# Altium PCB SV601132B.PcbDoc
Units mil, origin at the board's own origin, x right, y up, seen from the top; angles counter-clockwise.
Board outline 2180 x 2750 mil, 2 copper layers (Top Layer, Bottom Layer), stack 61.4 mil thick; 47 components, 16 nets, 82 pads, 27 vias.
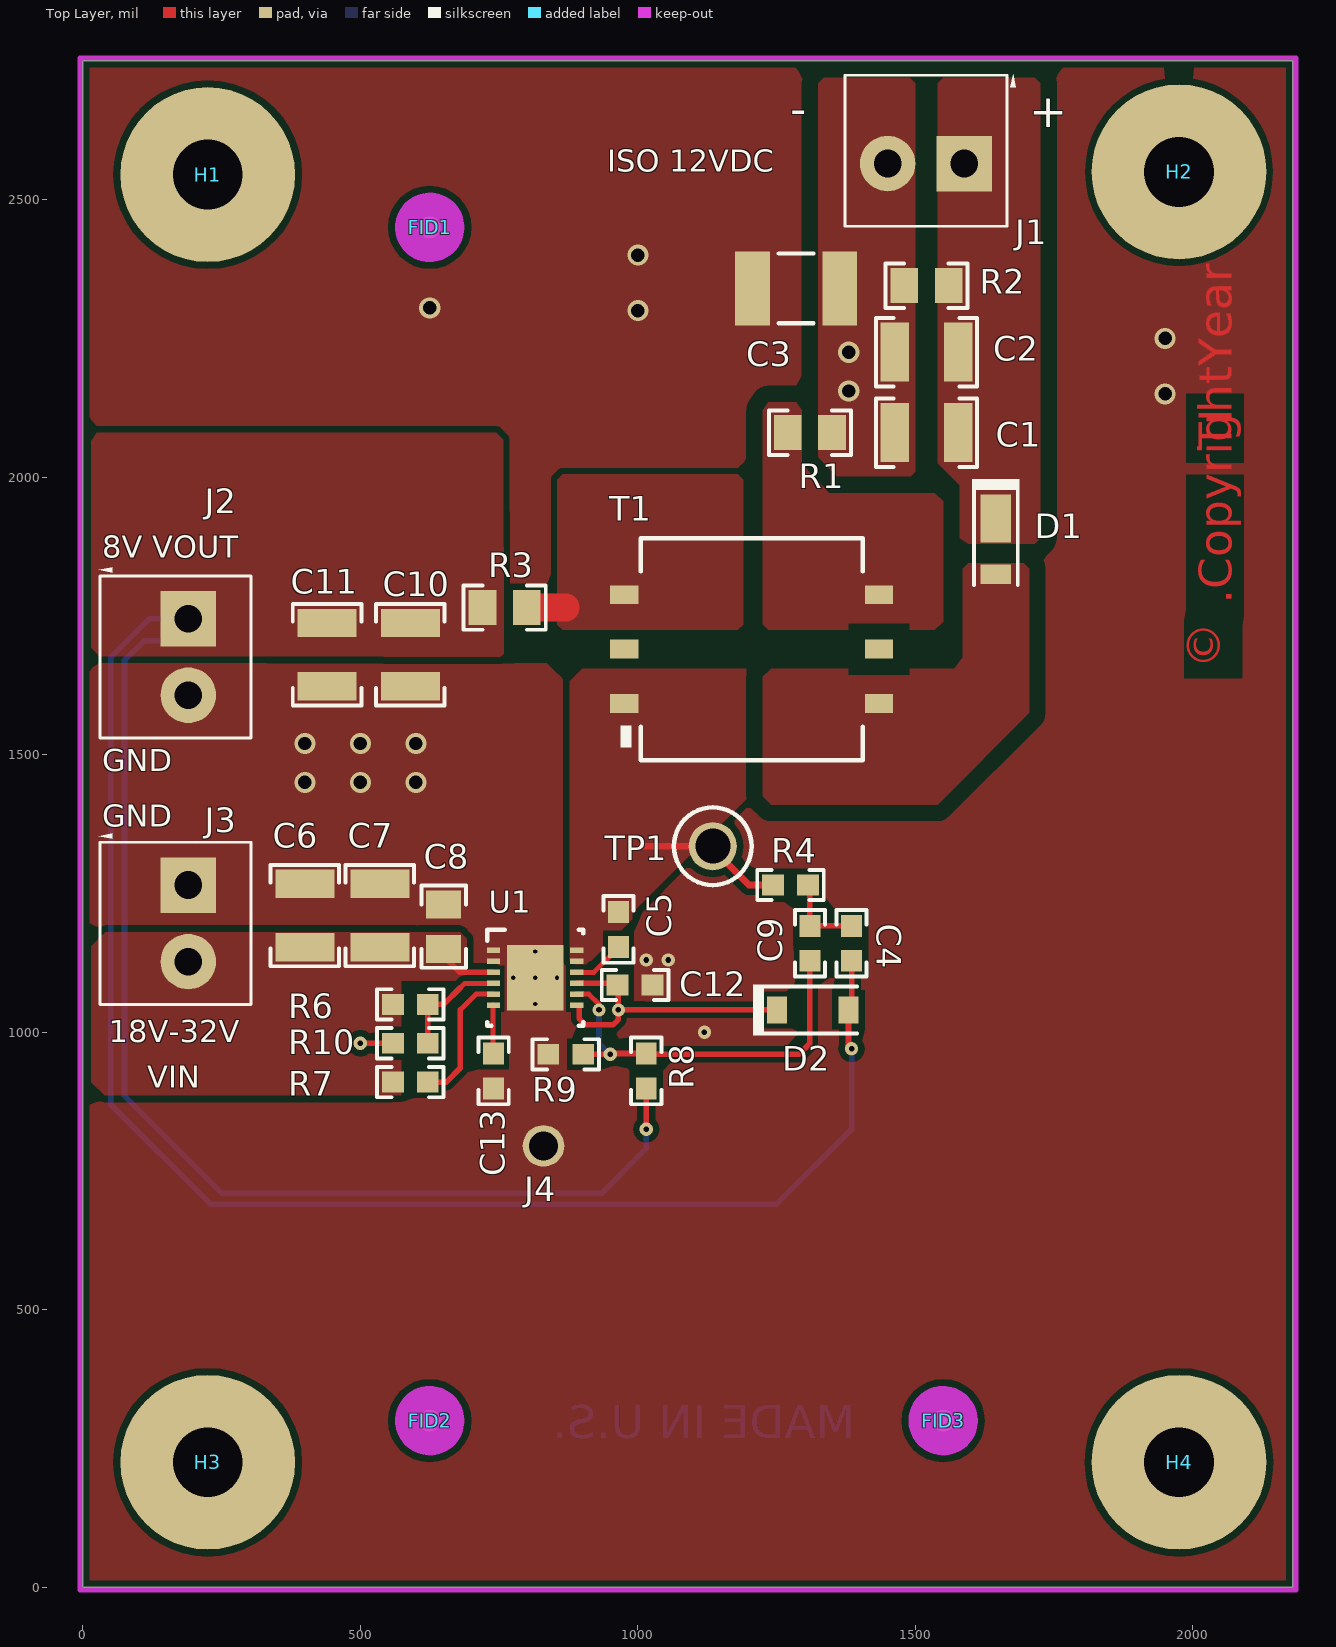
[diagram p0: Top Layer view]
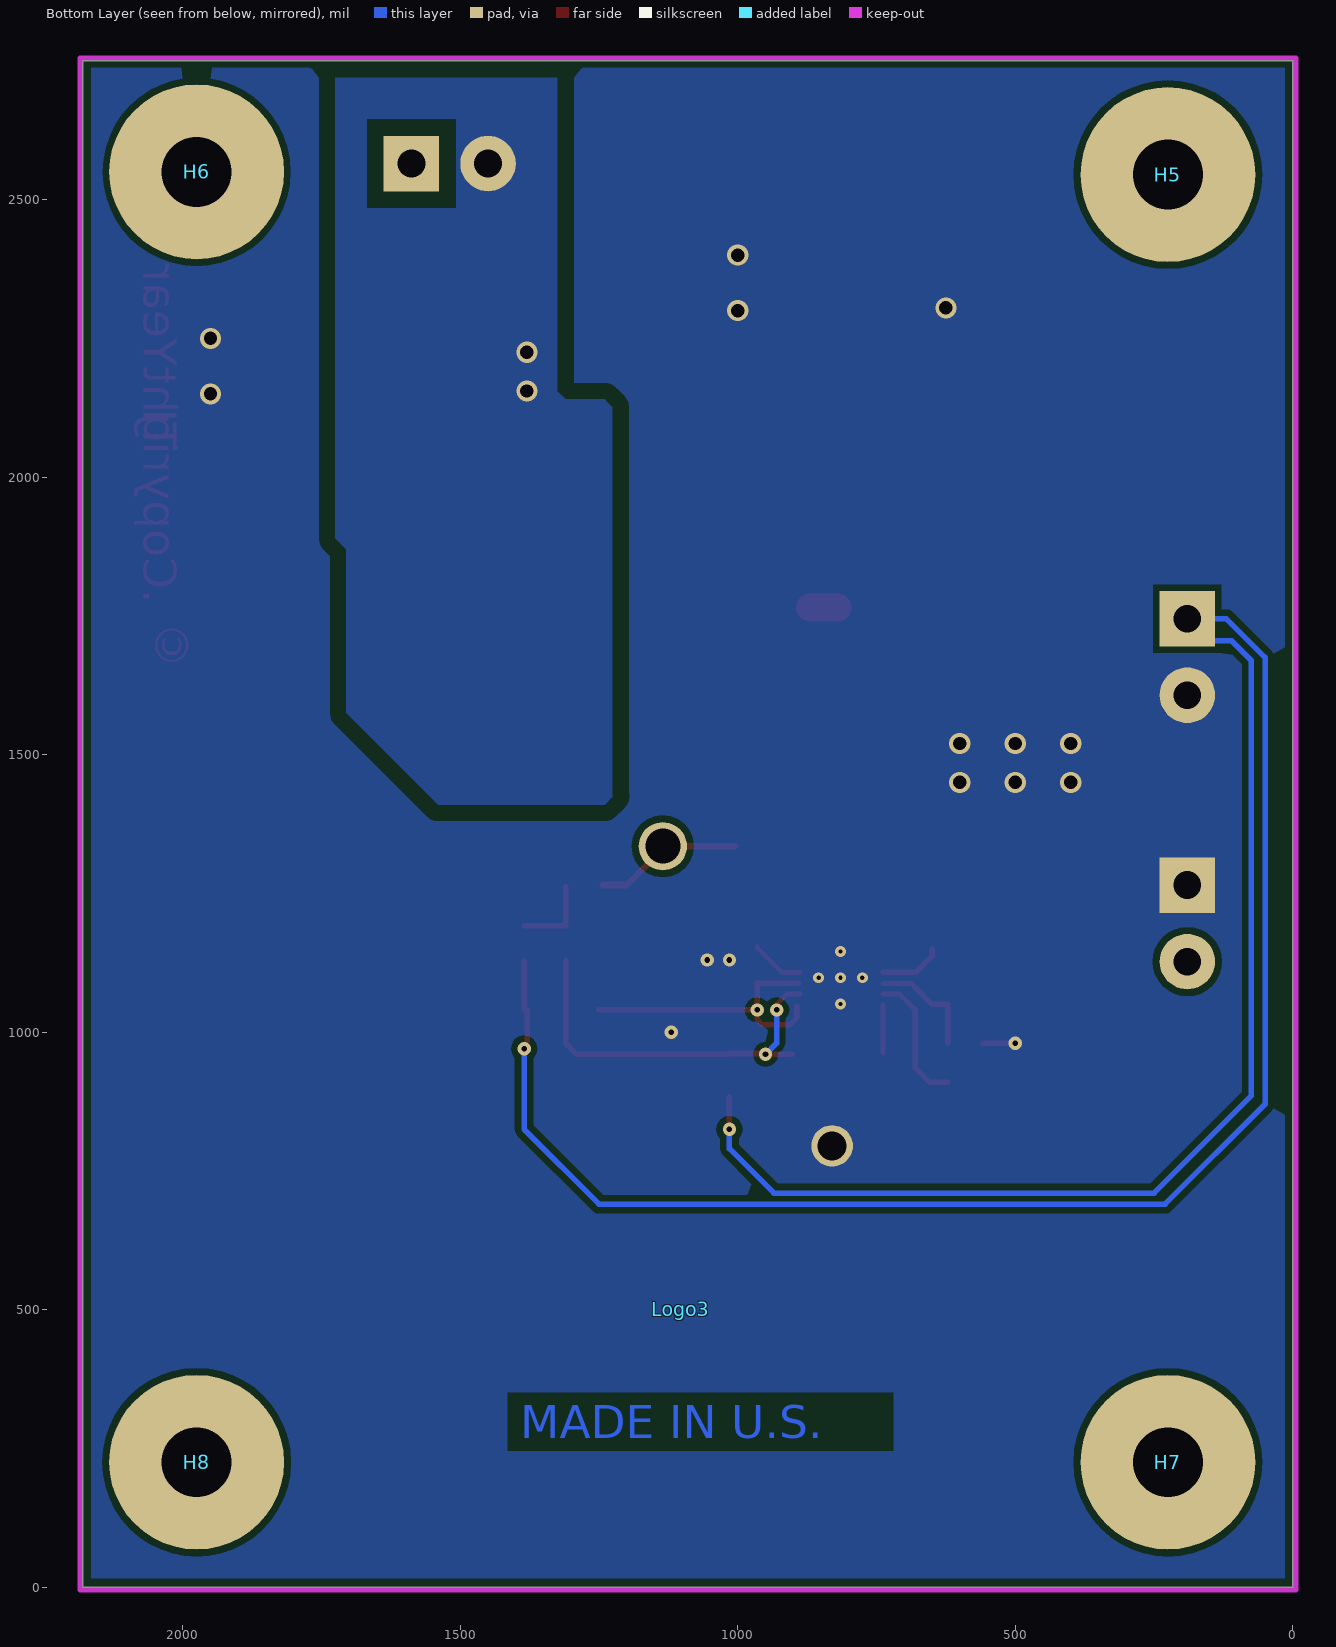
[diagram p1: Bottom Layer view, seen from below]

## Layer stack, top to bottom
Top Solder: solder mask 0.4, Solder Resist, Dk 3.5
Top Layer: signal copper 2.8
Dielectric1: core 55.8, FR-4, Dk 4.8
Bottom Layer: signal copper 2.8
Bottom Solder: solder mask 0.4, Solder Resist, Dk 3.5

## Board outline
0,0 0,2750 2180,2750 2180,0

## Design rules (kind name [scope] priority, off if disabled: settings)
AcuteAngle [All] p1: minimum=4.50000000000000E+0001 checktracksonly=FALSE
AssemblyTestPointUsage [All] p1: valid=2
Clearance "clearance U1" [HasFootprint('DNT0012B')] p1: gap=8 ignorepadtopadclearanceinfootprint=FALSE
Clearance [InNet('ISOGND')   or InNet('NetD1_2')    or   InNet('NetR1_1')      or InNet ('VOUTISO')] p2: gap=30 ignorepadtopadclearanceinfootprint=FALSE
Clearance Clearance_2 [InNet('NetR6_1')  or InNet('NetR7_1') or InNet('NetC6_1')    or   InNet('NetC13_1')     or InNet('NetC9_2')  or InNet('NetC12_1')       or InNet('NetC5_2')] p3: gap=10 ignorepadtopadclearanceinfootprint=FALSE
Clearance Clearance_1 [All] p4: gap=12 ignorepadtopadclearanceinfootprint=FALSE
Clearance Clearance_BoardEdge_MountingHoles [OnCopper and InComponentClass('Mounting Holes') vs IsKeepOut] p5: gap=30 ignorepadtopadclearanceinfootprint=FALSE
Clearance Clearance_BoardEdge_Poly [OnCopper and InPoly vs IsKeepOut] p6: gap=25 ignorepadtopadclearanceinfootprint=FALSE
Clearance Clearance_BoardEdge [OnCopper and Not InComponentClass('Logo') and not InComponentClass('FiducialMark') and not InRegion(100,500,4000,8000) and Not IsKeepOut vs IsKeepOut] p7: gap=40 ignorepadtopadclearanceinfootprint=FALSE
Clearance Clearance_Poly [InPolygon] p8: gap=12 ignorepadtopadclearanceinfootprint=FALSE
ComponentClearance ComponentClearance_Logo [InComponentClass('Logo')] p1: gap=50 collisioncheckmode=3 verticalgap=10 showdistances=FALSE
ComponentClearance ComponentClearance_ScrewToNut [(HasFootprint('NY PMS 440 0025 PH')) vs (HasFootprint('Keystone_1902C'))] p2: gap=5 collisioncheckmode=3 verticalgap=10 showdistances=FALSE
ComponentClearance ComponentClearance_MountingHoles [InComponentClass('Mounting Holes')] p3: gap=130 collisioncheckmode=3 verticalgap=100000 showdistances=FALSE
ComponentClearance ComponentClearance_SmallPassives [HasFootprint('0201*') or HasFootprint('0402*') or HasFootprint('0508') or HasFootprint('0603*') or HasFootprint('0612') or HasFootprint('0805*') or HasFootprint('0815*') or HasFootprint('0830*') or HasFootprint('1206*') or HasFootprint('1210*') or HasFootprint('1808*') or HasFootprint('1812*') or HasFootprint('1825*') or HasFootprint('2010*') or HasFootprint('2220*') or HasFootprint('2225*') or HasFootprint('2512*') or HasFootprint('2728*') or HasFootprint('3518*') vs HasFootprint('0201*') or HasFootprint('0402*') or HasFootprint('0508') or HasFootprint('0603*') or HasFootprint('0612') or HasFootprint('0805*') or HasFootprint('0815*') or HasFootprint('0830*') or HasFootprint('1206*') or HasFootprint('1210*') or HasFootprint('1808*') or HasFootprint('1812*') or HasFootprint('1825*') or HasFootprint('2010*') or HasFootprint('2220*') or HasFootprint('2225*') or HasFootprint('2512*') or HasFootprint('2728*') or HasFootprint('3518*')] p4: gap=20 collisioncheckmode=3 verticalgap=10 showdistances=FALSE
ComponentClearance ComponentClearance_THtoSMT [IsThruComponent vs IsSMTComponent] p5: gap=50 collisioncheckmode=3 verticalgap=30 showdistances=FALSE
ComponentClearance ComponentClearance_THtoTH [IsThruComponent vs IsThruComponent] p6: gap=118.11 collisioncheckmode=3 verticalgap=30 showdistances=FALSE
ComponentClearance [All] p7: gap=20 collisioncheckmode=3 verticalgap=10 showdistances=FALSE
ComponentOrientations [All] p1: allowedrotations=32
DiffPairsRouting [All] p1: maxlimit=100 minlimit=10 mostfreqgap=10 toplayer_minwidth=15 toplayer_maxwidth=15 toplayer_prefwidth=15 bottomlayer_minwidth=15 bottomlayer_maxwidth=15 bottomlayer_prefwidth=15 maxuncoupledlength=1000
FabricationTestPointUsage TestPointUsage [All] p1: valid=2 allowmultiple=FALSE
FabricationTestpoint Testpoint [All] p1: side=3 testpointundercomponent=TRUE minsize=40 maxsize=100 preferedsize=60 minholesize=0 maxholesize=40 preferedholesize=32 testpointgrid=1 allowsidetop=TRUE allowsidebottom=TRUE usegrid=TRUE gridtolerance=0.01
FanoutControl Fanout_LCC [IsLCC] p1: bgadir=Out bgaviamode=Centered fanoutstyle=Auto fanoutdirection=Alternating viagrid=1 // Fanout_LCC (Default Rule)
FanoutControl Fanout_BGA [IsBGA] p2: bgadir=Out bgaviamode=Centered fanoutstyle=Auto fanoutdirection=Alternating viagrid=1 // Fanout_BGA (Default Rule)
FanoutControl Fanout_Default [All] p4: bgadir=Out bgaviamode=Centered fanoutstyle=Auto fanoutdirection=Alternating viagrid=1 // Fanout_Default (Default Rule)
FanoutControl Fanout_Small [(CompPinCount < 5)] p5: bgadir=Out bgaviamode=Centered fanoutstyle=Auto fanoutdirection=OutThenIn viagrid=1 // Fanout_Small (Default Rule)
HoleSize [All] p1: absolutevalues=TRUE maxlimit=251 minlimit=7 maxpercent=80.000 minpercent=20.000
MinimumAnnularRing MinimumAnnularRing_ThermalPadVias [IsVia and InAnyComponent] p1: minimumring=5.91
MinimumAnnularRing [All] p2: minimumring=6
MinimumSolderMaskSliver MinimumSolderMaskSliver_Logo [InComponentClass('Logo') vs InComponentClass('Logo')] p1: minsoldermaskwidth=0.7
MinimumSolderMaskSliver [All] p2: minsoldermaskwidth=3.94
PlaneConnect [All] p1: planeconnectstyle=Direct reliefexpansion=10 reliefentries=4 reliefconductorwidth=10 reliefairgap=10
PolygonConnect PolygonConnect_2 [All vs IsNamedPolygon('Top Layer-No Net')] p1: connectstyle=Direct reliefconductorwidth=10 reliefentries=4 polygonreliefangle="90 Angle" airgapwidth=10
PolygonConnect PolygonConnect_1 [All vs IsNamedPolygon('Top Layer-No Net')] p2: connectstyle=Direct reliefconductorwidth=10 reliefentries=4 polygonreliefangle="90 Angle" airgapwidth=10
PolygonConnect [All] p3: connectstyle=Direct reliefconductorwidth=10 reliefentries=4 polygonreliefangle="90 Angle" airgapwidth=10
RoutingVias ThermalPadVias [IsVia and InAnyComponent] p1: holewidth=7.87 width=19.68 viastyle="Through Hole" minholewidth=7.87 minwidth=19.68 maxholewidth=12.99 maxwidth=23.62
RoutingVias [All] p2: holewidth=16 width=34 viastyle="Through Hole" minholewidth=7.87 minwidth=20 maxholewidth=40 maxwidth=65
SMDToCorner [All] p1: distance=30000
SilkToBoardRegionClearance [NOT ((IsComment OR IsDesignator) AND (Hide <> 'FAIL')) AND NOT InRegion (100,500,4000,8000)] p1:
SilkToSilkClearance [All] p1: silktosilkclearance=5
SilkToSolderMaskClearance SilkscreenOverComponentPads [IsPad] p1: minsilkscreentomaskgap=5 clearancetoexposedcopper=TRUE
SolderMaskExpansion [All] p1: expansion=1.97 istentingtop=FALSE
Width [All] p1: maxlimit=100 minlimit=6 preferedwidth=10 checkconnectedcopper=TRUE
15 further rules are at their usual default settings.

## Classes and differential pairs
component class AssemblyNote: ZZ1 ZZ2 ZZ3 ZZ4
component class FiducialMark: FID1 FID2 FID3
component class SV601132B_HW: FID1 FID2 FID3 H1 H2 H3 H4 H5 H6 H7 H8 Logo3 ZZ1 ZZ2 ZZ3 ZZ4
component class "Mounting Holes": H1 H2 H3 H4
component class SV601132B: C1 C2 C3 C4 C5 C6 C7 C8 C9 C10 C11 C12 C13 D1 D2 J1 J2 J3 J4 R1 R2 R3 R4 R6 R7 R8 R9 R10 T1 TP1 U1

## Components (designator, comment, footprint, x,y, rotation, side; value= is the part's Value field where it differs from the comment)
C1 "GRM32ER7YA106KA12L" 1210 1520,2080 r0 top
C2 "GRM32ER7YA106KA12L" 1210 1520,2225 r0 top
C3 "C4532X7R3D222K" 1812 1285,2340 r0 top
C4 "GRM188R71C102KA01D" 0603 1385,1160 r270 top
C5 "GRM188R71C103KA01D" 0603 965,1185 r270 top
C6 "GRM32ER72A225KA35K" 1210 400,1210 r90 top
C7 "GRM32ER72A225KA35K" 1210 535,1210 r90 top
C8 "GRM21BR72A474KA73L" 0805_HV 650,1190 r90 top
C9 "06033C104JAT2A" 0603 1310,1160 r270 top
C10 "GRM32ER7YA106KA12L" 1210 590,1680 r270 top
C11 "GRM32ER7YA106KA12L" 1210 440,1680 r270 top
C12 "C1608X7R1C105K" 0603 995,1085 r0 top
C13 "GRM188R71C823KA01D" 0603 740,930 r270 top
D1 "DFLS1100-7" powerDI123 1645,1875 r270 top
D2 "B0530W-7-F" SOD-123 1315,1040 r0 top
FID1 "Fiducial" Fiducial10-30 625,2450 r0 top
FID2 "Fiducial" Fiducial10-30 625,300 r0 top
FID3 "Fiducial" Fiducial10-30 1550,300 r0 top
H1 "NY PMS 440 0025 PH" "NY PMS 440 0025 PH" 225,2545 r0 top locked
H2 "NY PMS 440 0025 PH" "NY PMS 440 0025 PH" 1975,2550 r0 top locked
H3 "NY PMS 440 0025 PH" "NY PMS 440 0025 PH" 225,225 r0 top locked
H4 "NY PMS 440 0025 PH" "NY PMS 440 0025 PH" 1975,225 r0 top locked
H5 "1902C" Keystone_1902C 225,2545 r180 bottom locked
H6 "1902C" Keystone_1902C 1975,2550 r180 bottom locked
H7 "1902C" Keystone_1902C 225,225 r180 bottom locked
H8 "1902C" Keystone_1902C 1975,225 r180 bottom locked
J1 "ED555/2DS" TERM_BLK_ED555-2DS 1588,2565 r180 top
J2 "ED555/2DS" TERM_BLK_ED555-2DS 190,1745 r270 top
J3 "ED555/2DS" TERM_BLK_ED555-2DS 190,1265 r270 top
J4 "1040" CONN_1040 830,795 r0 top
Logo3 "FCC disclaimer" FCC_disclaimer_stacked 1103,501 r180 bottom
R1 "CRCW08050000Z0EA" 0805_HV 1310,2080 r0 top
R2 "CRCW08052K00JNEA" 0805_HV 1520,2345 r180 top
R3 "CRCW08050000Z0EA" 0805_HV 760,1765 r0 top
R4 "RC0603FR-0751K1L" 0603 1275,1265 r0 top
R6 "RC0603FR-07127KL" 0603 590,1050 r180 top
R7 "CRCW0603301KFKEA" 0603 590,910 r180 top
R8 "CRCW06036K04FKEA" 0603 1015,930 r270 top
R9 "CRCW06032K00FKEA" 0603 870,960 r0 top
R10 "CRCW060310K0FKEA" 0603 590,980 r0 top
T1 "750314597" WURTH_750314597 1205,1690 r90 top
TP1 "5014" Keystone5014 1135,1335 r0 top
U1 "LM5160ADNTR" DNT0012B 815,1098 r0 top
ZZ1 "Install label in silk screened box after final wash.  Text shall be 8 pt. font.  Text shall be per Label Table." AssemblyNoteLabel 77,3650 r0 top
ZZ2 "These assemblies are ESD sensitive, ESD precautions shall be observed." AssemblyNote 77,3528.45 r0 top
ZZ3 "These assemblies must be clean and free from flux and all contaminants. Use of no clean flux is not acceptable." AssemblyNote 77,3427.22 r0 top
ZZ4 "must comply with workmanship standards IPC-A-610 Class 2., unless otherwise specified." AssemblyNote 77,3326 r0 top

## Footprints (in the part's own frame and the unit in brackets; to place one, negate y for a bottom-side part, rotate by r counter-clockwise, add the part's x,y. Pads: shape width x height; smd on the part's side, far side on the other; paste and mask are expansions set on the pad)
0603 [mm] "0603 from SM-752 data"
  rect 1x0.95 smd: 1(-0.8,0) 2(0.8,0)
  silkscreen extent -1.52,-0.69 1.52,0.69, body extent -0.87,-0.47 0.87,0.47, height 0.85
0805_HV [mil] "0805 with 30mil clearance between pads"
  rect 50x63 smd: 1(-40,0) 2(40,0)
  silkscreen extent -74,-40 74,40, body extent -43,-29 43,29, height 43
1210 [mm] "1210 from SM-752 data"
  rect 1.3x2.7 smd: 1(-1.45,0) 2(1.45,0)
  silkscreen extent -2.32,-1.57 2.32,1.57, body extent -1.7,-1.35 1.7,1.35, height 1.35
1812 [mm]
  rect 1.6x3.4 smd: 1(-2,0) 2(2,0)
  silkscreen extent -0.8,-1.6 0.8,1.6, body extent -2.4,-1.7 2.4,1.7, height 1.35
AssemblyNote [mil] "Assembly Note"
AssemblyNoteLabel [mil] "Assembly Note for PCB Labels"
CONN_1040 [mil] "Test Point, PC  test point Terminal"
  round 75 hole 52: 1(0,0)
  body extent -55,-12 55,13, height 276
DNT0012B [mm] "SON, 12-Leads, Body 4x4mm, Pitch 0.5mm"
  rect 0.6x0.25 smd: 1(-1.9,1.25) 2(-1.9,0.75) 3(-1.9,0.25) 4(-1.9,-0.25) 5(-1.9,-0.75) 6(-1.9,-1.25) 7(1.9,-1.25) 8(1.9,-0.75) 9(1.9,-0.25) 10(1.9,0.25) 11(1.9,0.75) 12(1.9,1.25)
  rect 2.6x3 smd paste-1.3: 13(0,0)
  silkscreen extent -2.2,-2.2 2.2,2.2, body extent -2.05,-2.05 2.05,2.05, height 0.81
FCC_disclaimer_stacked [mil]
Fiducial10-30 [mm]
  round 1 smd paste-0.5 mask+1: 1(0,0)
  Top Layer keep-out circle w1.678: c0,0 r0.75
Keystone5014 [mil] "Keystone Multipurpose loops"
  round 87 hole 63: 1(0,0)
  silkscreen extent -70,-70 70,70, body extent -63,-63 63,62, height 319
Keystone_1902C [mil] "Hex Standoff, 4-40 threaded, nylon"
  body extent -145,-126 146,126, height 501
"NY PMS 440 0025 PH" [mm] "4-40 nylon screw and mounting hole"
  round 8 hole 3.2: 1(0,0)
  body extent -3.3,-3.3 3.3,3.3, height 2.69
powerDI123 [mm] "Diodes Inc recommended land pattern, document number DS30628 Rev. 6-2"
  rect 2.2x1.4 smd: 1(-1.275,0)
  rect 0.9x1.4 smd: 2(1.275,0)
  silkscreen extent -3.1,-1.09 1.76,1.09, body extent -2.38,-0.97 1.52,0.96, height 1
SOD-123 [mm] "On Semi recommended land pattern"
  rect 0.915x1.22 smd: 1(-1.637,0) 2(1.637,0)
  silkscreen extent -2.74,-1.17 2.03,1.17, body extent -1.93,-0.9 1.93,0.9, height 1.35
TERM_BLK_ED555-2DS [mil]
  rect 100x100 hole 50: 1(0,0)
  round 100 hole 50: 2(138,0)
  silkscreen extent -93,-161 215,113, body extent -69,-150 207,106, height 323
WURTH_750314597 [mil] "WURTH ELEKTRONIK"
  rect 34x51 smd: 1(-98,229.5) 2(0,229.5) 3(98,229.5) 4(98,-229.5) 5(0,-229.5) 6(-98,-229.5)
  silkscreen extent -200,-200 200,236, body extent -194,-250 193,250, height 339

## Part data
C1 C2 C10 C11: "CAP, CERM, 10uF, 35V, +/-10%, X7R, 1210"
C3: "CAP, CERM, 2200pF, 2000V, +/-10%, X7R, 1812"
C4: "CAP, CERM, 1000pF, 16V, +/-10%, X7R, 0603"
C5: "CAP, CERM, 0.01uF, 16V, +/-10%, X7R, 0603"
C6 C7: library part Capacitor, "CAP, CERM, 2.2uF, 100V, X7R, 10%, 1210"
C8: "CAP, CERM, 0.47uF, 100V, +/-10%, X7R, 0805"
C9: "CAP, CERM, 0.1uF, 25V, +/-5%, X7R, 0603"
C12: library part C1608X7R1C105K080AC, "CAP, CERM, 1 µF, 16 V, +/- 10%, X7R, 0603"
C13: "CAP, CERM, 0.082uF, 16V, +/-10%, X7R, 0603"
D1: "Diode, Schottky, 100V, 1A, PowerDI123"
D2: "Diode, Schottky, 30V, 0.5A, SOD-123"
FID1 FID2 FID3: "Fiducial mark.  There is nothing to buy or mount."
H1 H2 H3 H4: "Machine Screw, Round, #4-40 x 1/4, Nylon, Philips panhead"
H5 H6 H7 H8: "Standoff, Hex, 0.5\"L #4-40 Nylon"
J1 J2 J3: "Terminal Block, 6A, 3.5mm Pitch, 2-Pos, TH"
J4: "TEST POINT SLOTTED .118\", TH"
Logo3: library part FCC_disclaimer, "FCC_disclaimer"
R1 R3: "RES, 0 ohm, 5%, 0.125W, 0805"
R2: "RES, 2.0k ohm, 5%, 0.125W, 0805"
R4: "RES, 51.1k ohm, 1%, 0.1W, 0603"
R6: "RES, 127k ohm, 1%, 0.1W, 0603"
R7: "RES, 301k ohm, 1%, 0.1W, 0603"
R8: "RES, 6.04k ohm, 1%, 0.1W, 0603"
R9: "RES, 2.00k ohm, 1%, 0.1W, 0603"
R10: "RES, 10.0k ohm, 1%, 0.1W, 0603"
T1: "Transformer, 60uH, SMT"
TP1: "Test Point, Multipurpose, Yellow, TH"
U1: "Wide Input 65V, 1.5A Synchronous Step-Down DC-DC Converter, DNT0012B"
ZZ1: library part AssemblyNoteLabel
ZZ2 ZZ3 ZZ4: library part AssemblyNote

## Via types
v1: diameter 38, hole 24, Top Layer to Bottom Layer, 13 vias
v2: diameter 24, hole 10, Top Layer to Bottom Layer, 9 vias
v3: diameter 19.68, hole 7.87, Top Layer to Bottom Layer, 5 vias

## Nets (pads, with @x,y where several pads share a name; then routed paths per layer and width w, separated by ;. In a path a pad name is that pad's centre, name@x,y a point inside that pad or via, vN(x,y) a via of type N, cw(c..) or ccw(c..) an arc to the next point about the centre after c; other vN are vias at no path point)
GND: C3.1 C6.2 C7.2 C8.2 C10.2 C11.2 C12.2 C13.2 J2.2 J3.1 J4.1 R9.1 R10.1 U1.1 U1.2 U1.13 | length 58.5
  Top Layer w10: v2(500,980) R10.1
  other v1: 400,1450 500,1450 600,1450 400,1520 500,1520 600,1520 1950,2150 1950,2250 1000,2300 625,2305 1000,2400
  other v2: 1120,1000 1015,1130 1055,1130
  other v3: 815,1050.76 775.63,1098 815,1098 854.37,1098 815,1145.24
ISOGND: C1.1 C2.1 C3.2 J1.2 R1.2 R2.2
  other v1: 1380,2155 1380,2225
NetC4_1: C4.1 C9.1 R4.2 | length 145
  Top Layer w10: R4.2@1310,1261.5 C9.1 C4.1
NetC5_1: C5.1 R4.1 T1.1 TP1.1 U1.11 U1.12 | length 237.1
  Top Layer w12: 1005,1335 TP1.1 ; TP1.1@1155,1310 1200,1265 R4.1
NetC5_2: C5.2 U1.10 | length 96.6
  Top Layer w9: U1.10@888.28,1107.68 920.68,1107.68 965,1152 C5.2
NetC9_2: C9.2 R8.1 R9.2 U1.8 | length 709.9
  Top Layer w9: U1.8@888.28,1068.31 911.69,1068.31 930,1050 v2(930,1040)
  Top Layer w10: R9.2 v2(950,960) ; v2@951.5,961.5 R8.1 ; R8.1@1016.5,960 1290,960 1310,980 C9.2
  Bottom Layer w10: v2(930,1040) 930,980 v2(950,960)
NetC12_1: C12.1 D2.1 U1.7 U1.9 | length 524.4
  Top Layer w9.8: U1.9 C12.1@960.35,1088.16 ; 894,1025 905.9,1013.1 955.24,1013.1 965,1022.86 v2(965,1040) ; C12.1@962.24,1084.91 962.01,1087.99 C12.1@965,1087.99 ; C12.1@965,1083.5 v2(965,1040) ; D2.1 v2(965,1040)
  Top Layer w10: 894,1025 U1.7@894,1046.58
NetC13_1: C13.1 U1.6 | length 85.8
  Top Layer w9: C13.1@738.68,962.82 U1.6@738.68,1048.62
NetD1_2: D1.2 T1.6
NetR1_1: R1.1 T1.4
NetR3_2: R3.2 T1.3 | length 50
  Top Layer w50: R3.2@820,1765 870,1765
NetR6_1: R6.1 R10.2 U1.4 | length 202.9
  Top Layer w9: 680,1080 687.99,1087.99 U1.4@738.68,1087.99
  Top Layer w10: R10.2 R6.1 650,1050 680,1080
NetR7_1: R7.1 U1.5 | length 244.3
  Top Layer w9: 680,1040 708.31,1068.31 U1.5@738.68,1068.31
  Top Layer w10: R7.1 655,910 680,935 680,1040
VIN: C6.1 C7.1 C8.1 J3.2 R6.2 R7.2 U1.3 | length 113.8
  Top Layer w10: C8.1 650,1137 679.32,1107.68 U1.3@738.68,1107.68
VOUT: C4.2 C10.1 C11.1 D2.2 J2.1 R3.1 R8.2 | length 4774.9
  Top Layer w10: v2(1015,825) R8.2@1015,883.5 ; D2.2 1379.47,975.53 v2(1385,970) ; D2.2@1385,1040.53 C4.2
  Bottom Layer w10: J2.1@150,1745 120,1745 50,1675 50,870 230,690 1250,690 1385,825 v2(1385,970) ; J2.1 150,1705 110,1705 75,1670 75,885 250,710 935,710 1015,790 v2(1015,825)
VOUTISO: C1.2 C2.2 D1.1 J1.1 R2.1
pads on no net: FID1.1 FID2.1 FID3.1 H1.1 H2.1 H3.1 H4.1 T1.2 T1.5

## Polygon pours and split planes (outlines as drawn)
GND on Top Layer "Top Layer-No Net 5" (solid, remove dead copper, pour order 46): 10,2745 2170,2745 2170,10 10,10
VOUT on Top Layer "Top Layer-No Net 2" (solid, pour order 44): 30,1676.9 332,1676.9 758,1675 757.24,2066.99 745,2080 25,2080 15,2064.42 14.83,1692.92
NetR1_1 on Top Layer "Top Layer-No Net 6" (solid, remove dead copper, pour order 38): 1550,1739.47 1550,1956.53 1535,1971 1345,1971 1295,2024.06 1295,2120.53 1285,2135 1235,2135 1225,2120.53 1225,1734.65 1235,1725 1535,1725
VOUTISO on Top Layer "Top Layer-IVOUT" (solid, remove dead copper, pour order 40): 1725,1890 1715,1880 1595,1880 1580,1890 1580,1985 1540,2025 1540,2710 1555,2724 1710,2725 1725,2710
NetR3_2 on Top Layer "Top Layer-No Net 3" (solid, remove dead copper, pour order 41): 855,1734.33 865,1725 1180,1725 1190,1734.33 1190,1995.67 1180,2005 865,2005 855,1995.67
ISOGND on Top Layer "Top Layer-SGND" (solid, remove dead copper, pour order 42): 1500,2010 1500,2710 1485,2724 1340,2725 1325,2710 1325,2025 1350,2000 1490,2000
VIN on Top Layer "Top Layer-No Net 1" (solid, remove dead copper, pour order 43): 679.97,1180 599.87,1180 599.08,1180.97 40,1180 15,1155 15,910 40,885 573.3,885.97 573.3,1092.99 681.59,1092.99 692.32,1107.68 691.98,1168.06
NetD1_2 on Top Layer "Top Layer-ISW" (solid, remove dead copper, pour order 39): 1540,1410 1705,1575 1705,1835 1695,1845 1595,1845 1585,1835 1585,1675 1570,1655 1240,1655 1225,1640 1225,1425 1240,1410
NetC5_1 on Top Layer "Top Layer-No Net" (solid, remove dead copper, pour order 45): 877,1119.77 907.06,1120.01 990,1203.63 990,1215 1195,1420 1195,1655 900,1655 877,1632
GND on Bottom Layer "Top Layer-No Net 5" (solid, remove dead copper, pour order 47): 14.83,2740.17 2165.17,2740.17 2165.17,15.83 14.83,15.83
ISOGND on Bottom Layer "Bottom Layer-No Net" (solid, pour order 12): 1325,2740 1725,2740 1725,1890 1705,1870 1705,1835 1705,1575 1540,1410 1240,1410 1225,1425 1226,1426 1226,2121.98 1226,2126 1235,2135 1240,2140 1305,2140 1310,2140 1325,2155 1325,2710 1325,2740

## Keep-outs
Keep-Out Layer:
  lines w10: -5,-5 2185,-5 2185,2755 -5,2755 -5,-5

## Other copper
Top Layer:
  pour cut-out: 776.39,1713.54 777.16,1712.76 938,1712.76 938,1667.24 937.07,1666.3 868.41,1666.3 851.35,1649.24 835.59,1665 775,1665 775,1712.15 775.61,1712.76
  text "TI" at 2070,2048 h60 r90
  text ".CopyrightYear" at 2070,1772 h60 r90
  text "©" at 2070,1655 h105 r90
  text ".Layer_Name" at 577,-858.49 h60
Bottom Layer:
  text "MADE IN U.S." at 1392,268 h60
  text ".Layer_Name" at 577,-858.49 h60

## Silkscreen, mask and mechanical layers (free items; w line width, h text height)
Top Overlay:
  text "-" at 1275,2635 h60
  text "+" at 1705,2630 h60
  text "ISO 12VDC" at 945,2550 h40
  text "8V VOUT" at 35,1855 h40
  text "GND" at 35,1470 h40
  text "GND" at 35,1370 h40
  text "18V-32V" at 47,982 h40
  text "VIN" at 116,900 h40
  text ".Layer_Name" at 577,-858.49 h60
Bottom Overlay:
  text ".Layer_Name" at 577,-858.49 h60
Top Paste:
  text ".Layer_Name" at 577,-858.49 h60
Bottom Paste:
  text ".Layer_Name" at 577,-858.49 h60
Top Solder:
  rectangle: 1802,2152 1864,2285
  rectangle: 1643,2144 1707,2283
  rectangle: 1088,1420 1185,1570
  rectangle: 1227,1420 1325,1570
  rectangle: 1088,1818 1185,1965
  rectangle: 1230,1815 1328,1966
  text ".Layer_Name" at 577,-858.49 h60
  text ".Layer_Name" at 577,-858.49 h60
Bottom Solder:
  text ".Layer_Name" at 577,-858.49 h60
Drill Guide:
  text ".Layer_Name" at 577,-858.49 h60
M1 Board Outline:
  the board outline again, w10
  text ".Layer_Name" at 577,-858.49 h60
M2 Board Dimensions:
  rectangle: 124.5,-410.5 499.5,-285.5
  rectangle: -0.5,-285.5 124.5,-160.5
  lines w7: -0.5,-285.5 999.5,-285.5 ; 124.5,-410.5 124.5,-160.5 ; 249.5,-410.5 249.5,-160.5 ; 499.5,-410.5 499.5,-160.5 ; 749.5,-410.5 749.5,-160.5 ; -0.5,-410.5 -0.5,-160.5 999.5,-160.5 999.5,-410.5 -0.5,-410.5
  lines w10: -24.08,-485 -24.08,-465 ; 35.92,-495 -24.08,-475 ; 35.92,-455 -24.08,-475 ; 200,-475 -24.08,-475 ; 751.83,-475 975.92,-475 ; 915.92,-495 975.92,-475 ; 915.92,-455 975.92,-475 ; 975.92,-485 975.92,-465
  text "1000 (mil)" at 210,-510.99 h60
  text ".Layer_Name" at 577,-858.49 h60
M3 3D STEP Top:
  text ".Layer_Name" at 577,-858.49 h60
M4 3D STEP Bottom:
  text ".Layer_Name" at 577,-858.49 h60
M5 Assembly Top:
  lines w10: -292,-930.17 6308,-930.17 ; -292,-726.83 6310,-726.83 ; -292,-523.5 -292,-1133.5 3713,-1133.5 6310,-1133.5 6310,-523.5 -291.5,-523.5 -291.5,-1133.5 1284,-1133.5 ; 2173,-1133.5 2173,-523.5 ; 3440,-726.83 3440,-523.5 ; 4280,-726.83 4280,-523.5 ; 4902,-1140 4902,-937.17
  text "COMPONENTS MARKED 'DNP' SHOULD NOT BE POPULATED." at 1153.5,-318.5 h60
  text "ASSEMBLY VARIANT:" at 1153,-434 h60
  text ".VariantName" at 2189,-434 h60
  text "PCB VIEWED FROM TOP SIDE" at -228.5,-655.67 h60
  text "BOARD #:" at 2248,-655.67 h60
  text ".PRJ_Number" at 2793.5,-655.67 h60
  text "REV:" at 3638,-655.67 h60
  text ".PCB_Rev" at 3929.5,-655.67 h60
  text "SVN REV:" at 4476,-655.67 h60
  text ".VersionControl_RevNumber" at 4982,-655.67 h60
  text "IGNORE ->" at -228.5,-858.49 h60
  text "PLOT NAME =" at -228.5,-1064.34 h60
  text ".plot_File_Name" at 577,-1064.34 h60
  text "GENERATED    :" at 2250,-1064.34 h60
  text ".Print_Date" at 3119.5,-1064.34 h60
  text ".Print_Time" at 3848.5,-1064.34 h60
  text "TEXAS INSTRUMENTS" at 5113,-1064.34 h60
M6 Assembly Bottom:
  lines w10: -292.5,-727.33 6309.5,-727.33 ; -290.5,-930.67 6309.5,-930.67 ; 1115.5,-1140.5 1115.5,-937.67 ; 1737.5,-727.33 1737.5,-524 ; 2577.5,-727.33 2577.5,-524 ; 3844.5,-1134 3844.5,-524 ; 4733.5,-1134 6309,-1134 6309,-524 -292.5,-524 -292.5,-1134 2304.5,-1134 6309.5,-1134 6309.5,-524
  text "COMPONENTS MARKED 'DNP' SHOULD NOT BE POPULATED." at 6102,-318 h60
  text ".VariantName" at 5058,-434 h60
  text "ASSEMBLY VARIANT:" at 6097,-434 h60
  text ".VersionControl_RevNumber" at 1035.5,-656.17 h60
  text "SVN REV:" at 1541.5,-656.17 h60
  text ".PCB_Rev" at 2088,-656.17 h60
  text "REV:" at 2379.5,-656.17 h60
  text ".PRJ_Number" at 3224,-656.17 h60
  text "BOARD #:" at 3769.5,-656.17 h60
  text "PCB VIEWED FROM BOTTOM SIDE" at 6246,-656.17 h60
  text "IGNORE ->" at 2547.85,-858.49 h60
  text "TEXAS INSTRUMENTS" at 904.5,-1064.84 h60
  text ".Print_Time" at 2169,-1064.84 h60
  text ".Print_Date" at 2898,-1064.84 h60
  text "GENERATED    :" at 3767.5,-1064.84 h60
  text ".plot_File_Name" at 5440.5,-1064.84 h60
  text "PLOT NAME =" at 6246,-1064.84 h60
M9 Title Sheet:
  drawing of 57 lines, arcs and shapes, not listed
  text "1" at 739.84,8036.5 h70
  text "2" at 3235.5,8036.5 h70
  text "3" at 5724.84,8036.5 h70
  text "4" at 8231.51,8036.5 h70
  text "5" at 10730.5,8036.5 h70
  text "6" at 13235.5,8036.5 h70
  text "A" at -416.5,6893.5 h70
  text "A" at 14383.5,6893.5 h70
  text "B" at -416.5,4513.5 h70
  text "B" at 14383.5,4513.5 h70
  text "C" at -416.5,2138.5 h70
  text "C" at 14383.5,2138.5 h70
  text "PROJECT TITLE:" at 11343.5,277.5 h45
  text ".PRJ_Title" at 11393.5,144.17 h70
  text "DESIGNED FOR:" at 11343.5,-23.5 h45
  text ".PRJ_Customer" at 11393.5,-163.5 h70
  text "D" at -416.5,-231.5 h70
  text "D" at 14383.5,-231.5 h70
  text "FILE NAME:" at 11343.5,-323.5 h45
  text ".PCB_File_Name_No_Path" at 11393.5,-443.5 h70
  text "Texas Instruments (TI) and/or its licensors do not warrant the accuracy or completeness of this specification" at 6374,-605.34 h45
  text "ENGINEER:" at 11343.5,-613.5 h45
  text "LAYOUT BY:" at 12848.5,-613.5 h45
  text "or any information contained therein. TI and/or its licensors do not warrant that this design will meet" at 6329.01,-718 h45
  text ".PRJ_Engineer" at 11393.5,-768.49 h70
  text ".PCB_Layout" at 12899,-768.49 h70
  text "the specifications, will be suitable for your application or fit for any particular purpose, or will operate in" at 6329.01,-830.67 h45
  text ".Layer_Name" at 577,-858.49 h60
  text "ALTIUM DESIGNER VERSION:" at 12848.5,-923.5 h45
  text "an implementation. TI and/or its licensors do not warrant that the design is production worthy. You should" at 6329.01,-943.33 h45
  text "completely validate and test your design implementation to confirm the system functionality for your application." at 6374,-1056 h45
  text ".print_Scale" at 11393.5,-1056.83 h70
  text ".Application_BuildNumber" at 12899,-1056.83 h70
  text "1" at 739.84,-1263.5 h70
  text "2" at 3235.5,-1263.5 h70
  text "3" at 5724.84,-1263.5 h70
  text "4" at 8231.51,-1263.5 h70
  text "5" at 10730.5,-1263.5 h70
  text "6" at 13235.5,-1263.5 h70
M10 Fab Notes:
  drawing of 185 lines, arcs and shapes, not listed
  text "DESIGN INFORMATION" at 12378.02,5924 h60
  text "MIN. TRACK WIDTH:" at 11733.46,5744 h60
  text "8" at 12829.7,5744 h60
  text "MIL" at 12984.46,5744 h60
  text "MIN. CLEARANCE:" at 11733.46,5612 h60
  text "0.2" at 12769.7,5612 h60
  text "mm" at 12984.46,5612 h60
  text "MIN. VIA PAD SIZE:" at 11733.46,5480 h60
  text "24" at 12799.71,5480 h60
  text "MIL" at 12984.46,5480 h60
  text "0.05mm (2MIL)" at 12428.46,5338.29 h60
  text "MINIMUM ANNULAR RING" at 11404.23,5334 h60
  text "EXTERNAL" at 13136.46,5334 h60
  text "PER" at 11604.23,5216 h60
  text "IPC-D-275 CLASS 2 LEVEL C" at 11824.23,5216 h60
  text "MIL, HOLES" at 13312.46,5103.71 h60
  text "+/-" at 12920,5103 h60
  text "+/-" at 13774,5103 h60
  text "REGISTRATION TOLERANCES:" at 11404.23,5098 h60
  text "METAL" at 12604,5098 h60
  text "5" at 13180.2,5098 h60
  text "3" at 14013.2,5098 h60
  text "MIL" at 14129.46,5098 h60
  text "MATERIAL:" at 11329.46,4888.54 h60
  text "FR-4 High Tg" at 12315.9,4748.21 h60
  text "FR-408" at 11750.46,4739.64 h60
  text "X" at 12162.46,4739.64 h60
  text "OTHER" at 13238.46,4739.64 h60
  text "62 MIL (1.6mm) +/-10%" at 12070.56,4576.92 h60
  text "THICKNESS:" at 11404.23,4572.64 h60
  text "X" at 11942.4,4572.64 h60
  text "OTHER" at 13355.46,4572.64 h60
  text "TOLERANCE:" at 11404.23,4414.64 h60
  text "X" at 12243.53,4414.64 h60
  text "ANSI IPC-6012 TYPE 3 CLASS 2" at 12430.48,4414.64 h60
  text "OTHER +/-" at 12430.46,4258.64 h60
  text "BOW & TWIST:" at 11404.23,4101.64 h60
  text "X" at 12243.53,4101.64 h60
  text "ANSI IPC-6012 TYPE 3 CLASS 2" at 12430.48,4101.64 h60
  text "OTHER +/-" at 12430.46,3943.13 h60
  text "DRILLING:" at 11329.46,3804.64 h60
  text "REFERENCE:" at 11404.23,3687.64 h60
  text "X" at 12052.46,3687.64 h60
  text "AS SHOWN" at 12239.46,3687.64 h60
  text "X" at 12953.46,3687.64 h60
  text "NC_DRILL FILES" at 13090.46,3687.64 h60
  text "PTH MIN COPPER THICKNESS:" at 11404.23,3529.64 h60
  text "X" at 12754.46,3529.64 h60
  text "1MIL" at 12891.46,3529.64 h60
  text "OTHER" at 13388.46,3529.64 h60
  text "BOARD FINISH:" at 11329.46,3370.64 h60
  text "SILKSCREEN:" at 11484.68,3252.64 h60
  text "X" at 12433.46,3252.64 h60
  text "TOP" at 12559.46,3252.64 h60
  text "X" at 12943.46,3252.64 h60
  text "BOTTOM" at 13070.46,3252.64 h60
  text "SILKSCREEN COLOR:" at 11484.68,3085.64 h60
  text "X" at 12432.42,3085.64 h60
  text "WHITE" at 12559.46,3085.64 h60
  text "OTHER" at 13070.46,3085.64 h60
  text "SOLDER RESIST COLOR:" at 11484.68,2915.64 h60
  text "X" at 12052.42,2756.44 h60
  text "GREEN" at 12179.46,2756.44 h60
  text "BLUE" at 12770.46,2756.44 h60
  text "OTHER" at 13308.46,2756.44 h60
  text "IMMERSION GOLD (ENIG)" at 12390.46,2567.92 h60
  text "ENEPIG" at 13728,2564.64 h60
  text "SURFACE FINISH:" at 11329.46,2563.64 h60
  text "X" at 12203.51,2563.64 h60
  text "IMM. TIN/SILVER OR EQUIV" at 11659,2406.64 h60
  text "OTHER" at 13090.46,2406.64 h60
  text "ARRAY/PANEL:" at 11329.46,2227.64 h60
  text "CUT AND TRIM PER MECH LAYER 1" at 12390.46,2223.35 h60
  text "X" at 13067,2074 h60
  text "N.C. ROUTE" at 12390.46,2071.64 h60
  text "V. SCORE" at 13256.46,2071.64 h60
  text "CERTIFICATION:" at 11329.46,1934.64 h60
  text "MATERIALS AND WORKMANSHIP FOR ALL PCBS" at 12054.46,1934.64 h60
  text "TO MEET OR EXCEED THE REQUIREMENTS OF:" at 12054.46,1836.64 h60
  text "X" at 11680.96,1700.13 h60
  text "ANSI IPC-A-600F CLASS ->" at 11819.96,1700.13 h60
  text "X" at 13459.02,1700.13 h60
  text "2" at 13577.96,1700.14 h60
  text "1" at 13262.96,1698.64 h60
  text "3" at 13931.96,1698.64 h60
  text "X" at 11683.02,1540.64 h60
  text "UL 94V-0" at 11819.96,1540.64 h60
  text "X" at 12495.02,1540.64 h60
  text "RoHS" at 12631.96,1540.64 h60
  text "OTHER" at 13276.36,1540.64 h60
  text "PER ORDER" at 13673.42,1540.64 h60
  text "ADDITIONAL REQUIREMENTS:" at 11329.46,1399.64 h60
  text "MICROSECTION:" at 11404.23,1284.64 h60
  text "YES" at 12309.96,1284.64 h60
  text "REQUIRED" at 13171.46,1128.49 h60
  text "BARE BOARD ELEC. TEST:" at 11404.23,1125.64 h60
  text "NONE" at 12709.96,1125.64 h60
  text "X" at 13044.46,1125.64 h60
  text "PER ORDER" at 13763.46,1125.64 h60
  text "MANUFACTURER'S UL:" at 11404.23,968.64 h60
  text "RAIL" at 12569.96,964.35 h60
  text "METAL" at 13061.77,964.35 h60
  text "X" at 13437,964 h60
  text "SILK" at 13573.46,964.35 h60
  text ".Layer_Name" at 577,-858.49 h60
M11 Gerber Information:
  lines w10: -292,-930.17 6308,-930.17 ; -292,-726.83 6310,-726.83 ; -292,-523.5 -292,-1133.5 3713,-1133.5 6310,-1133.5 6310,-523.5 -291.5,-523.5 -291.5,-1133.5 1284,-1133.5 ; 2173,-1133.5 2173,-523.5 ; 3440,-726.83 3440,-523.5 ; 4280,-726.83 4280,-523.5 ; 4902,-1140 4902,-937.17
  text "ALL ARTWORK VIEWED FROM TOP SIDE" at -228.5,-655.67 h60
  text "BOARD #:" at 2248,-655.67 h60
  text ".PRJ_Number" at 2793.5,-655.67 h60
  text "REV:" at 3638,-655.67 h60
  text ".PCB_Rev" at 3929.5,-655.67 h60
  text "SVN REV:" at 4476,-655.67 h60
  text ".VersionControl_RevNumber" at 4982,-655.67 h60
  text "LAYER NAME =" at -228.5,-858.49 h60
  text "PLOT NAME =" at -228.5,-1064.34 h60
  text ".plot_File_Name" at 577,-1064.34 h60
  text "GENERATED    :" at 2250,-1064.34 h60
  text ".Print_Date" at 3119.5,-1064.34 h60
  text ".Print_Time" at 3848.5,-1064.34 h60
  text "TEXAS INSTRUMENTS" at 5113,-1064.34 h60
M12 Stackup:
  drawing of 191 lines, arcs and shapes, not listed
  text "Layer" at 9833.24,7842.5 h60
  text "Name" at 10243.15,7842.5 h60
  text "Material" at 11172.9,7842.5 h60
  text "Thickness" at 12032.66,7842.5 h60
  text "Constant" at 12682.5,7842.5 h60
  text "Board Layer Stack" at 13252.36,7842.5 h60
  text "Top Overlay" at 10243.15,7722.5 h60
  text "Top Solder" at 10243.15,7602.5 h60
  text "Solder Resist" at 11172.9,7602.5 h60
  text "0.40mil" at 12032.66,7602.5 h60
  text "3.5" at 12682.5,7602.5 h60
  text "1" at 9833.24,7482.5 h60
  text "Top Layer" at 10243.15,7482.5 h60
  text "2.80mil" at 12032.66,7482.5 h60
  text "Dielectric1" at 10243.15,7362.5 h60
  text "FR-4" at 11172.9,7362.5 h60
  text "55.80mil" at 12032.66,7362.5 h60
  text "4.8" at 12682.5,7362.5 h60
  text "2" at 9833.24,7242.5 h60
  text "Bottom Layer" at 10243.15,7242.5 h60
  text "2.80mil" at 12032.66,7242.5 h60
  text "Bottom Solder" at 10243.15,7122.5 h60
  text "Solder Resist" at 11172.9,7122.5 h60
  text "0.40mil" at 12032.66,7122.5 h60
  text "3.5" at 12682.5,7122.5 h60
  text "Bottom Overlay" at 10243.15,7002.5 h60
  text ".Layer_Name" at 577,-858.49 h60
M13 Component Bodies Top:
  text ".Layer_Name" at 577,-858.49 h60
M14 Component Bodies Bottom:
  text ".Layer_Name" at 577,-858.49 h60
M15 Courtyards Top:
  text ".Layer_Name" at 577,-858.49 h60
M16 Courtyards Bottom:
  text ".Layer_Name" at 577,-858.49 h60
Drill Drawing:
  text ".legend" at 3262.5,415.5 h60
  text "Drill Table" at 3287.5,230.5 h60
  text ".Layer_Name" at 577,-858.49 h60

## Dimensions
0,0 to 0,2750 on M2 Board Dimensions
0,0 to 2180,0 on M2 Board Dimensions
